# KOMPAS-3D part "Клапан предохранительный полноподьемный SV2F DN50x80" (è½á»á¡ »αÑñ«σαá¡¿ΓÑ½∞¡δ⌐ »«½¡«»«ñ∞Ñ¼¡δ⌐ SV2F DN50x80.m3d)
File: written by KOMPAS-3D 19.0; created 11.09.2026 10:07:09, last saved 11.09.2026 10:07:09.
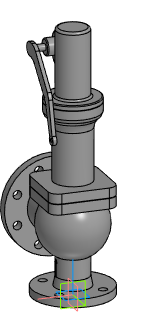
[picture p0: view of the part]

Document properties: Автор: elist; Организация: HP; Полное имя файла: Z:\3.Личные\sachek\Dendor\_3D для проектировщиков\5.9 SV2F. Клапан предохранительный полноподьемный\SV2F_STP\Клапан предохранительный полноподьемный SV2F DN50x80.m3d

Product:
- Part/product: Клапан предохранительный полноподьемный SV2F DN50x80

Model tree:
1. Операция без истории:1  (labels: Клапан предохранительный полноподьемный SV2F DN50x80)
